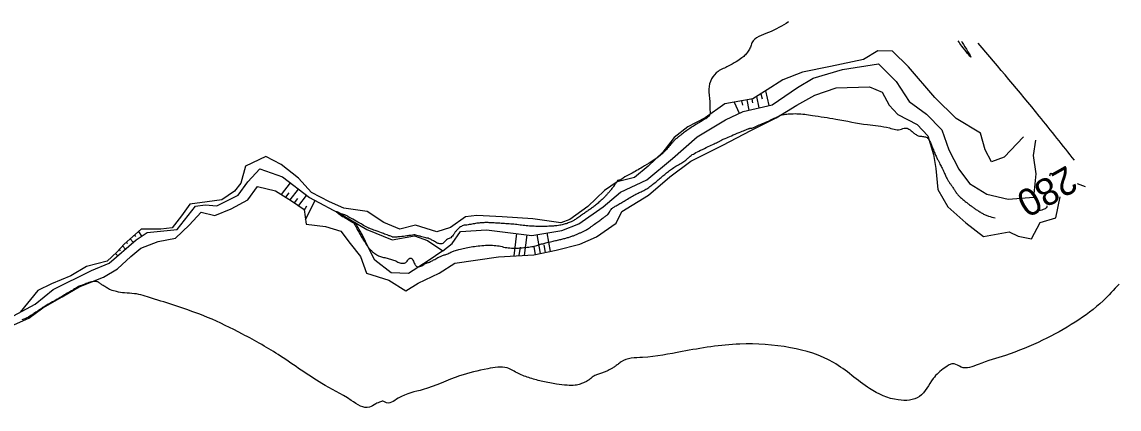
# Model space of a CAD drawing. Extents: x -475575 to -473225, y -1116053 to -1114104.
# Drawn here: x -473729.7 to -473568.7, y -1114786.5 to -1114729.7 of the extents above; entities that cross this region are included whole.
import ezdxf

# ---------------------------------------------------------------- set-up
doc = ezdxf.new("R2010")
doc.units = 0
for name, color, linetype in [('Vrstevnice_hlavni', 7, 'Continuous'), ('Vrstevnice_popis', 7, 'Continuous'), ('Vrstevnice_vedlejsi', 7, 'Continuous'), ('Vrstva_10', 7, 'Continuous')]:
    doc.layers.add(name, color=color, linetype=linetype)

msp = doc.modelspace()

# ---------------------------------------------------------------- linework, layer by layer
at = {"layer": 'Vrstevnice_hlavni'}
msp.add_line((-473574.83, -1114753.4), (-473573.68, -1114753.83), dxfattribs=at)
for points in [[(-473617.2, -1114729.7), (-473620.15, -1114731.27), (-473622.56, -1114732.78), (-473622.79, -1114733.42), (-473623.11, -1114733.99), (-473623.53, -1114734.51), (-473624.04, -1114734.98), (-473624.87, -1114735.54), (-473626.04, -1114736.2), (-473627.53, -1114736.95), (-473628.49, -1114738.07), (-473628.89, -1114739.54), (-473628.76, -1114741.38), (-473628.73, -1114742.66), (-473628.81, -1114743.4), (-473628.99, -1114743.6), (-473629.15, -1114743.75), (-473629.29, -1114743.86), (-473629.41, -1114743.94), (-473629.73, -1114744.13), (-473630.26, -1114744.45), (-473630.99, -1114744.88), (-473631.67, -1114745.32), (-473632.3, -1114745.76), (-473632.88, -1114746.21), (-473633.33, -1114746.55), (-473633.64, -1114746.8), (-473633.82, -1114746.94), (-473634.1, -1114747.24), (-473634.5, -1114747.68), (-473635, -1114748.28), (-473635.5, -1114748.81), (-473635.99, -1114749.27), (-473636.46, -1114749.65), (-473637.35, -1114750.23), (-473638.64, -1114751.01), (-473640.34, -1114751.98), (-473641.47, -1114752.62), (-473642.05, -1114752.94), (-473642.06, -1114752.94), (-473642.09, -1114752.94), (-473642.15, -1114752.95), (-473642.23, -1114752.96), (-473642.29, -1114752.99), (-473642.33, -1114753.03), (-473642.34, -1114753.09), (-473642.46, -1114753.28), (-473642.69, -1114753.6), (-473643.04, -1114754.06), (-473643.37, -1114754.48), (-473643.69, -1114754.85), (-473643.99, -1114755.19), (-473644.36, -1114755.56), (-473644.78, -1114755.95), (-473645.27, -1114756.38), (-473645.75, -1114756.77), (-473646.23, -1114757.12), (-473646.7, -1114757.45), (-473647.19, -1114757.79), (-473647.71, -1114758.16), (-473648.24, -1114758.54), (-473648.7, -1114758.83), (-473649.09, -1114759.04), (-473649.39, -1114759.15), (-473649.69, -1114759.26), (-473649.98, -1114759.35), (-473650.26, -1114759.43), (-473650.59, -1114759.51), (-473650.97, -1114759.58)], [(-473591.82, -1114732.54), (-473591.73, -1114732.69), (-473590.44, -1114734.87), (-473591.74, -1114733.26), (-473592.29, -1114732.49)], [(-473575.23, -1114750), (-473580.41, -1114743.51), (-473589.36, -1114732.82)], [(-473622.72, -1114745.29), (-473622.57, -1114745.27), (-473622.09, -1114745.08), (-473621.29, -1114744.74), (-473620.16, -1114744.24), (-473619.3, -1114743.84), (-473618.72, -1114743.56), (-473618.41, -1114743.39), (-473617.85, -1114743.27), (-473617.03, -1114743.19), (-473615.96, -1114743.16), (-473613.7, -1114743.41), (-473610.25, -1114743.95), (-473605.62, -1114744.77), (-473602.4, -1114745.26), (-473600.61, -1114745.43), (-473600.23, -1114745.27), (-473599.81, -1114745.31), (-473599.34, -1114745.55), (-473598.82, -1114746), (-473598.37, -1114746.31), (-473597.99, -1114746.46), (-473597.68, -1114746.48), (-473597.38, -1114746.52), (-473597.12, -1114746.58), (-473596.87, -1114746.68), (-473596.6, -1114747), (-473596.32, -1114747.54), (-473596.01, -1114748.31), (-473595.73, -1114748.98), (-473595.48, -1114749.54), (-473595.26, -1114750), (-473595.06, -1114750.39), (-473594.89, -1114750.72), (-473594.74, -1114750.99), (-473594.57, -1114751.35), (-473594.35, -1114751.8), (-473594.11, -1114752.36), (-473593.87, -1114752.83), (-473593.62, -1114753.23), (-473593.38, -1114753.56), (-473593.13, -1114753.92), (-473592.86, -1114754.32), (-473592.58, -1114754.76), (-473592.24, -1114755.18), (-473591.83, -1114755.57), (-473591.37, -1114755.95), (-473590.93, -1114756.3), (-473590.51, -1114756.62), (-473590.11, -1114756.91), (-473589.7, -1114757.2), (-473589.26, -1114757.48), (-473588.8, -1114757.76), (-473588.32, -1114758), (-473587.84, -1114758.19), (-473586.85, -1114758.47)], [(-473676.78, -1114764.22), (-473676.12, -1114764.36), (-473675.47, -1114764.54), (-473674.84, -1114764.78), (-473674.22, -1114765.07), (-473673.69, -1114765.11), (-473673.25, -1114764.91), (-473672.9, -1114764.46), (-473672.59, -1114764.37), (-473672.31, -1114764.64), (-473672.06, -1114765.26), (-473671.72, -1114765.58), (-473671.28, -1114765.6), (-473670.74, -1114765.31), (-473670.35, -1114765.11), (-473670.11, -1114765.01), (-473670.01, -1114764.99), (-473669.73, -1114764.87), (-473669.28, -1114764.63), (-473668.66, -1114764.29), (-473668.17, -1114764.05), (-473667.82, -1114763.91), (-473667.61, -1114763.87), (-473667.36, -1114763.78), (-473667.07, -1114763.65), (-473666.75, -1114763.47), (-473666.25, -1114763.28), (-473665.57, -1114763.08), (-473664.72, -1114762.88), (-473663.78, -1114762.71), (-473662.76, -1114762.57), (-473661.65, -1114762.47), (-473660.62, -1114762.48), (-473659.67, -1114762.58), (-473658.79, -1114762.78), (-473657.85, -1114762.89), (-473656.84, -1114762.89), (-473655.77, -1114762.79), (-473654.87, -1114762.67), (-473654.14, -1114762.51), (-473653.58, -1114762.33), (-473652.96, -1114762.16), (-473652.3, -1114762), (-473651.58, -1114761.83), (-473650.92, -1114761.68), (-473650.31, -1114761.53), (-473649.76, -1114761.39), (-473649.25, -1114761.23), (-473648.77, -1114761.07), (-473648.33, -1114760.89), (-473647.92, -1114760.71), (-473647.53, -1114760.54), (-473647.16, -1114760.37), (-473646.7, -1114760.1), (-473646.14, -1114759.72), (-473645.49, -1114759.25), (-473644.91, -1114758.83), (-473644.41, -1114758.47), (-473643.99, -1114758.17), (-473643.68, -1114757.89), (-473643.46, -1114757.62), (-473643.35, -1114757.37), (-473643.11, -1114757.1), (-473642.74, -1114756.82), (-473642.24, -1114756.53), (-473641.66, -1114756.19), (-473641.01, -1114755.8), (-473640.27, -1114755.36), (-473639.59, -1114754.99), (-473638.97, -1114754.67), (-473638.41, -1114754.42), (-473637.84, -1114754.08), (-473637.25, -1114753.65), (-473636.64, -1114753.14), (-473636.05, -1114752.65), (-473635.49, -1114752.18), (-473634.96, -1114751.74), (-473634.37, -1114751.3), (-473633.72, -1114750.87), (-473633, -1114750.45), (-473632.41, -1114750.07), (-473631.95, -1114749.71), (-473631.61, -1114749.39), (-473631, -1114748.99), (-473630.12, -1114748.53), (-473628.98, -1114748), (-473628.1, -1114747.58), (-473627.48, -1114747.27), (-473627.12, -1114747.08), (-473626.49, -1114746.78), (-473625.59, -1114746.4), (-473624.42, -1114745.91), (-473623.6, -1114745.57), (-473623.13, -1114745.39), (-473623, -1114745.35), (-473622.86, -1114745.31), (-473622.72, -1114745.29)], [(-473578.38, -1114752.06), (-473578.66, -1114751.96), (-473578.77, -1114751.97), (-473578.83, -1114752.05), (-473578.89, -1114752.34)], [(-473579.28, -1114756.7), (-473579.35, -1114756.97), (-473579.52, -1114757.11), (-473579.82, -1114757.24), (-473580.67, -1114757.48)], [(-473650.97, -1114759.58), (-473651.38, -1114759.63), (-473651.99, -1114759.68), (-473652.8, -1114759.7), (-473653.79, -1114759.71), (-473654.75, -1114759.68), (-473655.68, -1114759.61), (-473656.59, -1114759.5), (-473657.51, -1114759.4), (-473658.43, -1114759.32), (-473659.37, -1114759.26), (-473660.21, -1114759.21), (-473660.95, -1114759.17), (-473661.6, -1114759.15), (-473662.26, -1114759.18), (-473662.95, -1114759.25), (-473663.66, -1114759.38), (-473664.21, -1114759.47), (-473664.6, -1114759.53), (-473664.82, -1114759.54), (-473665.07, -1114759.63), (-473665.33, -1114759.78), (-473665.62, -1114760.01), (-473665.89, -1114760.28), (-473666.16, -1114760.61), (-473666.41, -1114760.98), (-473666.65, -1114761.26), (-473666.89, -1114761.44), (-473667.13, -1114761.52), (-473667.38, -1114761.68), (-473667.63, -1114761.9), (-473667.91, -1114762.19), (-473668.27, -1114762.27), (-473668.74, -1114762.15), (-473669.31, -1114761.82), (-473669.75, -1114761.59), (-473670.08, -1114761.45), (-473670.29, -1114761.42), (-473670.6, -1114761.35), (-473671.01, -1114761.24), (-473671.54, -1114761.08), (-473671.91, -1114760.98), (-473672.13, -1114760.94), (-473672.2, -1114760.96), (-473672.57, -1114761.02), (-473673.23, -1114761.1), (-473674.18, -1114761.22), (-473674.88, -1114761.28), (-473675.3, -1114761.27), (-473675.47, -1114761.2), (-473675.92, -1114761.03), (-473676.66, -1114760.75), (-473677.69, -1114760.37), (-473678.42, -1114760.1), (-473678.84, -1114759.94), (-473678.96, -1114759.89), (-473679.39, -1114759.66), (-473680.12, -1114759.24), (-473681.16, -1114758.64), (-473681.89, -1114758.23), (-473682.31, -1114758.02), (-473682.42, -1114758), (-473682.51, -1114757.98), (-473682.6, -1114757.96), (-473682.66, -1114757.93), (-473682.83, -1114757.85), (-473683.09, -1114757.74), (-473683.46, -1114757.57), (-473683.58, -1114757.55), (-473683.46, -1114757.68), (-473683.1, -1114757.94), (-473682.84, -1114758.13), (-473682.68, -1114758.23), (-473682.62, -1114758.25), (-473682.41, -1114758.37), (-473682.04, -1114758.59), (-473681.52, -1114758.91), (-473681.16, -1114759.14), (-473680.95, -1114759.29), (-473680.92, -1114759.34), (-473680.78, -1114759.58), (-473680.56, -1114760), (-473680.23, -1114760.61), (-473679.9, -1114761.19), (-473679.57, -1114761.73), (-473679.22, -1114762.25), (-473678.99, -1114762.6), (-473678.88, -1114762.77), (-473678.88, -1114762.78), (-473678.87, -1114762.79), (-473678.85, -1114762.83), (-473678.82, -1114762.88), (-473678.65, -1114763.04), (-473678.34, -1114763.32), (-473677.9, -1114763.7), (-473677.38, -1114764.01), (-473676.78, -1114764.22)]]:
    msp.add_spline(points, degree=3, dxfattribs=at)
at = {"layer": 'Vrstevnice_vedlejsi'}
msp.add_spline([(-473568.69, -1114768.16), (-473571.04, -1114770.63), (-473575.13, -1114773.75), (-473579.91, -1114776.42), (-473585.36, -1114778.63), (-473589.35, -1114779.95), (-473591.86, -1114780.36), (-473592.91, -1114779.88), (-473594.27, -1114780.44), (-473595.97, -1114782.04), (-473597.98, -1114784.68), (-473601.09, -1114785.18), (-473605.29, -1114783.51), (-473610.58, -1114779.69), (-473616.93, -1114777.51), (-473624.34, -1114776.98), (-473632.81, -1114778.08), (-473638.62, -1114778.94), (-473641.76, -1114779.57), (-473642.25, -1114779.95), (-473642.7, -1114780.28), (-473643.13, -1114780.56), (-473643.53, -1114780.78), (-473643.99, -1114780.99), (-473644.51, -1114781.18), (-473645.09, -1114781.37), (-473645.62, -1114781.61), (-473646.11, -1114781.92), (-473646.56, -1114782.29), (-473647.11, -1114782.59), (-473647.76, -1114782.84), (-473648.51, -1114783.02), (-473649.68, -1114783.02), (-473651.25, -1114782.84), (-473653.24, -1114782.48), (-473655.1, -1114781.97), (-473656.84, -1114781.3), (-473658.47, -1114780.48), (-473661.34, -1114780.59), (-473665.46, -1114781.65), (-473670.83, -1114783.65), (-473674.48, -1114784.93), (-473676.4, -1114785.51), (-473676.61, -1114785.38), (-473677.06, -1114785.45), (-473677.76, -1114785.74), (-473678.71, -1114786.25), (-473681.36, -1114785.25), (-473685.71, -1114782.74), (-473691.75, -1114778.74), (-473697.33, -1114775.51), (-473702.45, -1114773.06), (-473707.09, -1114771.38), (-473710.67, -1114770.22), (-473713.19, -1114769.58), (-473714.64, -1114769.47), (-473715.81, -1114769.28), (-473716.68, -1114769.03), (-473717.26, -1114768.7), (-473717.76, -1114768.4), (-473718.18, -1114768.12), (-473718.54, -1114767.86), (-473719.03, -1114767.79), (-473719.66, -1114767.89), (-473720.44, -1114768.17), (-473720.98, -1114768.38), (-473721.3, -1114768.5), (-473721.38, -1114768.54), (-473721.7, -1114768.72), (-473722.25, -1114769.05), (-473723.04, -1114769.52), (-473723.87, -1114770.02), (-473724.74, -1114770.53), (-473725.67, -1114771.05), (-473726.29, -1114771.41), (-473726.62, -1114771.6), (-473726.66, -1114771.62), (-473726.89, -1114771.78), (-473727.32, -1114772.07), (-473727.95, -1114772.49), (-473728.41, -1114772.8), (-473728.7, -1114772.99), (-473728.83, -1114773.06), (-473729.16, -1114773.21), (-473729.7, -1114773.44)], degree=3, dxfattribs=at)
at = {"layer": 'Vrstva_10'}
for p, q in [((-473621.24, -1114740.23), (-473621.07, -1114740.99)), ((-473620.57, -1114739.8), (-473620.08, -1114741.97)), ((-473625.19, -1114741.49), (-473624.42, -1114743.1)), ((-473624.08, -1114741.28), (-473623.94, -1114741.89)), ((-473623.34, -1114741.15), (-473623, -1114742.64)), ((-473622.6, -1114741.01), (-473622.47, -1114741.59)), ((-473621.92, -1114740.65), (-473621.54, -1114742.3)), ((-473691.61, -1114755.03), (-473690.3, -1114753.32)), ((-473690.97, -1114755.42), (-473690.46, -1114754.77)), ((-473690.32, -1114755.82), (-473689.11, -1114754.24)), ((-473689.7, -1114756.24), (-473689.22, -1114755.62)), ((-473689.08, -1114756.66), (-473687.92, -1114755.15)), ((-473688.26, -1114757.39), (-473687.88, -1114756.67)), ((-473688.09, -1114758.67), (-473686.64, -1114755.92)), ((-473713.82, -1114761.53), (-473713.38, -1114762.04)), ((-473713.18, -1114760.97), (-473713.03, -1114761.21)), ((-473712.61, -1114760.47), (-473712.17, -1114761.16)), ((-473657.47, -1114764.04), (-473657.06, -1114760.76)), ((-473655.95, -1114763.96), (-473655.57, -1114760.95)), ((-473653.61, -1114763.68), (-473654.09, -1114760.91)), ((-473652.15, -1114763.37), (-473652.61, -1114760.65)), ((-473715.43, -1114763.11), (-473715.29, -1114763.27)), ((-473714.93, -1114762.55), (-473714.51, -1114763.03)), ((-473714.39, -1114762.02), (-473714.21, -1114762.23)), ((-473656.71, -1114764), (-473656.55, -1114762.74)), ((-473654.35, -1114763.83), (-473654.54, -1114762.71)), ((-473652.88, -1114763.52), (-473653.07, -1114762.43)), ((-473715.95, -1114763.66), (-473715.64, -1114764.01))]:
    msp.add_line(p, q, dxfattribs=at)
for points in [[(-473582.72, -1114746.56), (-473585.53, -1114749.53), (-473587.42, -1114750.24), (-473588.32, -1114748.48), (-473589.03, -1114746.02), (-473592.61, -1114743.86), (-473595.75, -1114740.78), (-473599.59, -1114736.3), (-473601.95, -1114733.98), (-473604.1, -1114733.96), (-473606.21, -1114735.22), (-473611.06, -1114736.22), (-473615.14, -1114737.08), (-473618.02, -1114738.18), (-473620.33, -1114739.65), (-473622.45, -1114740.98), (-473626.53, -1114741.74), (-473629.41, -1114743.76), (-473631.95, -1114745.07), (-473633.96, -1114746.67), (-473635.65, -1114748.79), (-473637.8, -1114750.87), (-473639.8, -1114752.53), (-473642.33, -1114753.14), (-473644.21, -1114754.42)], [(-473644.4, -1114756.83), (-473641.85, -1114754.7), (-473637.99, -1114752.89), (-473634.2, -1114749.73), (-473630.61, -1114746.56), (-473626.47, -1114744.08), (-473623.86, -1114742.83), (-473619.62, -1114741.86), (-473615.86, -1114739.34), (-473613.57, -1114737.93), (-473609.26, -1114736.7), (-473603.99, -1114735.86), (-473601.39, -1114738.45), (-473599.51, -1114741.38), (-473596.93, -1114743.22), (-473594.72, -1114745.51), (-473593.69, -1114748.47), (-473592.18, -1114751.31), (-473590.62, -1114753.43), (-473588.08, -1114754.98), (-473584.97, -1114755.73), (-473581.21, -1114755.4), (-473580.84, -1114751.98), (-473581.27, -1114749.31), (-473580.88, -1114747.05)], [(-473641.66, -1114757.51), (-473637.76, -1114755.1), (-473634.6, -1114752.43), (-473631.55, -1114750.15), (-473626.85, -1114747.79), (-473622.74, -1114745.64), (-473619.01, -1114743.79), (-473615.98, -1114741.9), (-473613.35, -1114740.43), (-473610.19, -1114739.39), (-473605.31, -1114739.23), (-473603.44, -1114740.02), (-473602.44, -1114741.91), (-473601.14, -1114743.28), (-473598.33, -1114744.73), (-473596.73, -1114746.41), (-473595.9, -1114749.14), (-473595.56, -1114751.23), (-473595.31, -1114754.28), (-473593.83, -1114756.81), (-473591.17, -1114759.16), (-473588.6, -1114761.18), (-473584.8, -1114760.5), (-473583.51, -1114761.15), (-473581.55, -1114761.52), (-473580.26, -1114759.14), (-473577.97, -1114758.45), (-473577.31, -1114755.38)], [(-473644.21, -1114754.42), (-473646.66, -1114756.78), (-473649.27, -1114758.68), (-473650.59, -1114759.16), (-473654.71, -1114758.58), (-473659.24, -1114758.29), (-473662.93, -1114758.11), (-473664.62, -1114758.28), (-473666.81, -1114759.87), (-473668.82, -1114760.51), (-473671.92, -1114759.51), (-473674.22, -1114760.12), (-473676.57, -1114759.14), (-473679.04, -1114757.54), (-473682.44, -1114757.03), (-473684.55, -1114756.1), (-473687.18, -1114754.74), (-473689.13, -1114752.65), (-473691.64, -1114750.61), (-473693.91, -1114749.44), (-473696.87, -1114750.86), (-473697.59, -1114753.36), (-473698.48, -1114754.51), (-473700.37, -1114755.8), (-473702.51, -1114756.08), (-473705.06, -1114756.46), (-473706.3, -1114758.15), (-473707.64, -1114759.92), (-473709.29, -1114760.12), (-473712.18, -1114760.09), (-473714.71, -1114762.3), (-473715.77, -1114763.49), (-473717.21, -1114764.81), (-473720.22, -1114765.61), (-473722.5, -1114766.97), (-473725.38, -1114768.12), (-473727.35, -1114769.13), (-473729.96, -1114772.29)], [(-473730.95, -1114772.85), (-473727.77, -1114771.11), (-473725.1, -1114768.97), (-473719.49, -1114766.19), (-473716.9, -1114765.11), (-473712.94, -1114761.66), (-473711.31, -1114760.61), (-473706.91, -1114760.17), (-473704.24, -1114756.75), (-473702.79, -1114756.53), (-473701.1, -1114756.68), (-473697.96, -1114755.1), (-473696.57, -1114753.18), (-473694.78, -1114751.28), (-473691.44, -1114752.45), (-473687.49, -1114755.48), (-473682.54, -1114758.09), (-473679.09, -1114760.14), (-473675.38, -1114761.66), (-473672.07, -1114761.07), (-473670.19, -1114761.78), (-473667.92, -1114763.27), (-473666.57, -1114762.21), (-473665.34, -1114760.45), (-473661.5, -1114760.2), (-473654.86, -1114761.04), (-473650.45, -1114760.29), (-473647.97, -1114759.34), (-473644.4, -1114756.83)], [(-473731.23, -1114774.3), (-473728.69, -1114773.16), (-473726.64, -1114771.67), (-473723.78, -1114770.03), (-473721.29, -1114768.56), (-473717.75, -1114767.15), (-473715.67, -1114765.94), (-473713.71, -1114764.13), (-473712.26, -1114762.91), (-473709.7, -1114761.91), (-473707.18, -1114761.43), (-473705.16, -1114759.52), (-473703.41, -1114757.62), (-473701.41, -1114758.1), (-473699.01, -1114757.13), (-473696.56, -1114755.82), (-473695.11, -1114753.84), (-473692.48, -1114754.5), (-473690.12, -1114755.94), (-473688.29, -1114757.22), (-473687.99, -1114759.36), (-473685.16, -1114759.73), (-473682.91, -1114760.42), (-473681.53, -1114762.21), (-473680.03, -1114764.13), (-473679.14, -1114766.59), (-473675.85, -1114767.62), (-473673.34, -1114769.14), (-473671.54, -1114768.05), (-473668.47, -1114766.56), (-473666.19, -1114765.11), (-473659.76, -1114764.17), (-473654.59, -1114763.88), (-473651.31, -1114763.19), (-473647.8, -1114762.33), (-473645.38, -1114761.25), (-473642.5, -1114759.25), (-473641.66, -1114757.51)], [(-473667.92, -1114763.27), (-473670.09, -1114764.77), (-473672.99, -1114766.64), (-473675.51, -1114766.52), (-473677.91, -1114764.64), (-473678.87, -1114762.77), (-473679.69, -1114761.08), (-473680.81, -1114759.12)]]:
    msp.add_lwpolyline(points, dxfattribs=at)

# ---------------------------------------------------------------- texts
at = {"layer": 'Vrstevnice_popis'}
msp.add_text(' 280 ', height=4, rotation=209.3995, dxfattribs=at).set_placement((-473575.03, -1114749.94))

doc.saveas('drawing.dxf')
